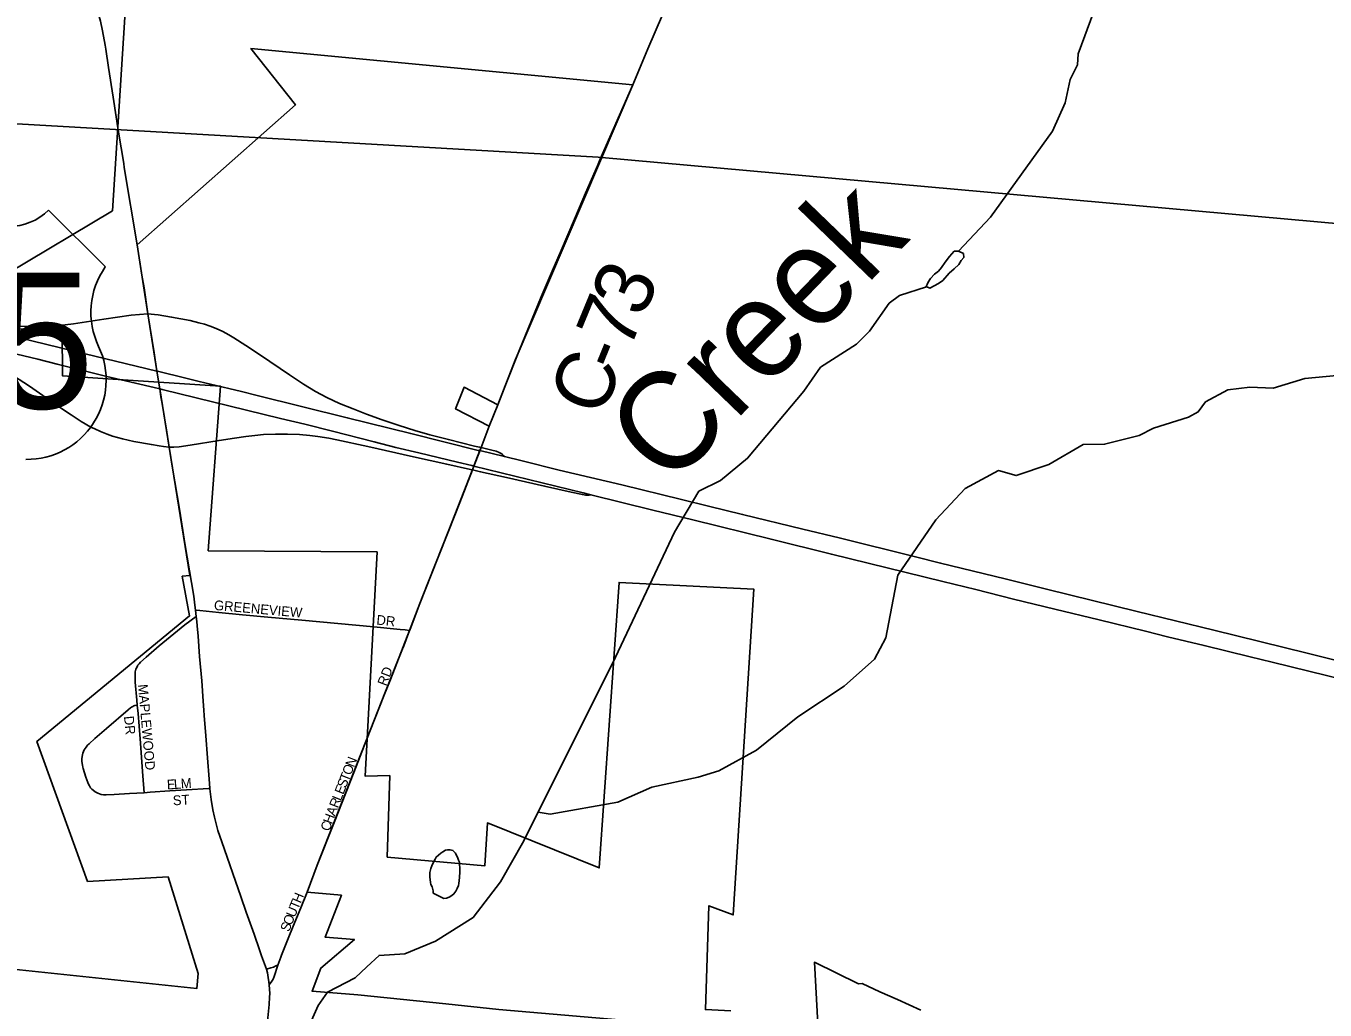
# Model space of a CAD drawing. Extents: x -5.4 to 49.9, y 13.2 to 48.4.
# Drawn here: x 29.333 to 30.593, y 43.891 to 44.845 of the extents above; entities that cross this region are included whole.
import ezdxf

# ---------------------------------------------------------------- set-up
doc = ezdxf.new("R2010")
doc.units = 0
for name, color, linetype in [('GM_X_City_Street', 7, 'Continuous'), ('GM_X_City_Street_Text', 7, 'Continuous'), ('GM_X_Corporation', 7, 'Continuous'), ('GM_X_County_Road', 7, 'Continuous'), ('GM_X_County_Road_Text', 7, 'Continuous'), ('GM_X_Interchange_Ramps', 7, 'Continuous'), ('GM_X_Major_River', 7, 'Continuous'), ('GM_X_Major_River_Text', 7, 'Continuous'), ('GM_X_Minor_Lake', 7, 'Continuous'), ('GM_X_Minor_River', 7, 'Continuous'), ('GM_X_State_Route', 7, 'Continuous'), ('GM_X_Township', 7, 'Continuous'), ('GM_X_US_Route', 7, 'Continuous'), ('GM_X_US_Shield', 7, 'Continuous')]:
    doc.layers.add(name, color=color, linetype=linetype)

msp = doc.modelspace()

# ---------------------------------------------------------------- linework, layer by layer
at = {"layer": 'GM_X_City_Street'}
for points in [[(29.4977, 44.2784), (29.502, 44.278), (29.5205, 44.2761), (29.5434, 44.2739), (29.5679, 44.2716), (29.6008, 44.2686), (29.6356, 44.2654), (29.6705, 44.2621), (29.693, 44.26), (29.6963, 44.2596), (29.701, 44.2591), (29.7053, 44.2586)], [(29.7053, 44.2586), (29.7055, 44.259), (29.7153, 44.2849)], [(29.4412, 44.1863), (29.4407, 44.1911), (29.4392, 44.2084), (29.4391, 44.2148), (29.4391, 44.2171), (29.4392, 44.2186), (29.4394, 44.2197), (29.4399, 44.2212), (29.4407, 44.2228), (29.4414, 44.2242), (29.4419, 44.225), (29.4431, 44.2264), (29.4444, 44.2278), (29.4498, 44.2328), (29.4626, 44.2436), (29.4874, 44.2641), (29.4983, 44.2721)], [(29.6985, 44.2409), (29.6997, 44.2438), (29.7053, 44.2586)], [(29.5812, 43.9436), (29.5877, 43.9598), (29.5925, 43.9719), (29.6, 43.9896), (29.6061, 44.0047), (29.6157, 44.0309), (29.6322, 44.0725), (29.6511, 44.121), (29.6636, 44.1526), (29.682, 44.1994), (29.6985, 44.2409)], [(29.448, 44.1013), (29.4338, 44.1004), (29.4189, 44.0994), (29.411, 44.0991), (29.4086, 44.0993), (29.4064, 44.0996), (29.4046, 44.1001), (29.403, 44.1007), (29.4017, 44.1014), (29.4003, 44.1022), (29.3984, 44.1037), (29.3971, 44.1048), (29.396, 44.1061), (29.3949, 44.1078), (29.394, 44.1097), (29.3932, 44.1113), (29.3914, 44.1163), (29.3901, 44.1205), (29.3887, 44.1248), (29.3884, 44.1261), (29.3881, 44.1279), (29.3879, 44.1295), (29.3876, 44.1318), (29.3876, 44.134), (29.3878, 44.1365), (29.3881, 44.1381), (29.3885, 44.1396), (29.3891, 44.1414), (29.3899, 44.1429), (29.3906, 44.1443), (29.3916, 44.1456), (29.393, 44.1473), (29.3945, 44.1488), (29.4001, 44.1538), (29.4115, 44.1635), (29.4324, 44.1816), (29.4346, 44.1835), (29.4356, 44.1842), (29.4368, 44.1849), (29.438, 44.1854), (29.439, 44.1858), (29.4405, 44.1861), (29.4412, 44.1863)], [(29.448, 44.1013), (29.4466, 44.1177), (29.4442, 44.1535), (29.4421, 44.1781), (29.4412, 44.1863)], [(29.5117, 44.1056), (29.5106, 44.1055), (29.4889, 44.1042), (29.4727, 44.103), (29.4539, 44.1017), (29.448, 44.1013)], [(29.5665, 43.9303), (29.5708, 43.9315), (29.5733, 43.9322), (29.5756, 43.9333), (29.5777, 43.9342)], [(29.5691, 43.9149), (29.5718, 43.9186), (29.5729, 43.9204), (29.5739, 43.923), (29.5777, 43.9342)], [(29.5777, 43.9342), (29.5804, 43.9418), (29.5812, 43.9436)]]:
    msp.add_lwpolyline(points, dxfattribs=at)
at = {"layer": 'GM_X_Corporation'}
for points in [[(29.3154, 44.6047), (29.4173, 44.6657), (29.4494, 45.1735)], [(29.2715, 43.9353), (29.4989, 43.9114), (29.5002, 43.926), (29.4712, 44.0196), (29.3931, 44.0152), (29.344, 44.151), (29.492, 44.2727), (29.4849, 44.3112), (29.4923, 44.3118), (29.4722, 44.4364), (29.4632, 44.493), (29.4603, 44.5103), (29.4516, 44.5657), (29.441, 44.6327), (29.5946, 44.7683), (29.5515, 44.8229), (29.9217, 44.7877), (29.8078, 44.5206), (29.7907, 44.4775), (29.7582, 44.4945), (29.7499, 44.4734), (29.7826, 44.4566), (29.7746, 44.4361), (29.7434, 44.3558), (29.7176, 44.2907), (29.7153, 44.2849), (29.7053, 44.2586), (29.6867, 44.2112), (29.6803, 44.1951), (29.6497, 44.1173), (29.6157, 44.0309), (29.6061, 44.0047), (29.6392, 44.0018), (29.6233, 43.9613), (29.6518, 43.959), (29.6194, 43.9312), (29.6107, 43.9088), (29.6551, 43.9053), (29.7403, 43.8965), (29.7917, 43.8912), (29.9386, 43.8783)], [(30.0169, 43.8897), (29.9921, 43.8909), (29.9955, 43.9916), (30.0191, 43.9827), (30.039, 44.2987), (29.9085, 44.3052), (29.8892, 44.0283), (29.7807, 44.072), (29.7782, 44.0303), (29.6837, 44.0388), (29.6861, 44.1179), (29.6623, 44.1172), (29.6738, 44.3348), (29.5101, 44.3359), (29.522, 44.4955), (29.4373, 44.5011), (29.3686, 44.5056), (29.3684, 44.5486), (29.3122, 44.5522)], [(30.2009, 43.8905), (30.1785, 43.9007), (30.1611, 43.9081), (30.1441, 43.9164), (30.1407, 43.9159), (30.0978, 43.9368), (30.1172, 43.5785)]]:
    msp.add_lwpolyline(points, dxfattribs=at)
at = {"layer": 'GM_X_County_Road'}
for points in [[(29.9217, 44.7877), (29.9364, 44.8225), (29.9506, 44.8556), (29.9779, 44.9189), (29.9868, 44.9401), (29.994, 44.9586), (30.001, 44.9779), (30.0071, 44.9962), (30.0139, 45.0188), (30.0224, 45.046), (30.0463, 45.1218), (30.0595, 45.1646), (30.0669, 45.1887)], [(29.8874, 44.7093), (29.8901, 44.7156), (29.9217, 44.7877)], [(29.876, 44.6828), (29.8874, 44.7093)], [(29.7907, 44.4775), (29.7981, 44.4958), (29.8112, 44.5293), (29.8329, 44.5821), (29.8436, 44.6072), (29.8522, 44.6272), (29.8651, 44.6574), (29.876, 44.6828)], [(29.7826, 44.4566), (29.7907, 44.4775)], [(29.7153, 44.2849), (29.7325, 44.3282), (29.743, 44.3548), (29.7539, 44.3826), (29.7662, 44.4143), (29.7676, 44.418), (29.7689, 44.4214), (29.7734, 44.433), (29.7746, 44.436), (29.7826, 44.4566)]]:
    msp.add_lwpolyline(points, dxfattribs=at)
at = {"layer": 'GM_X_Interchange_Ramps'}
for points in [[(29.4516, 44.5657), (29.4352, 44.5643), (29.4087, 44.5606), (29.3794, 44.5559), (29.3713, 44.5549), (29.3624, 44.554), (29.3541, 44.5536), (29.3422, 44.5532), (29.328, 44.5538), (29.3153, 44.555), (29.3041, 44.5563), (29.2957, 44.5579), (29.2846, 44.56), (29.2094, 44.5769), (29.1748, 44.5845), (29.1419, 44.5917), (29.1104, 44.5986), (29.0873, 44.6039), (29.0812, 44.6051), (29.0773, 44.6056), (29.0752, 44.6056), (29.072, 44.6049)], [(29.7974, 44.4272), (29.7957, 44.4287), (29.7946, 44.4298), (29.7921, 44.4313), (29.7891, 44.4324), (29.785, 44.4336), (29.7746, 44.436), (29.7731, 44.4364), (29.7683, 44.4375), (29.7429, 44.4438), (29.7249, 44.4483), (29.7105, 44.4524), (29.6951, 44.4573), (29.6786, 44.4629), (29.6634, 44.4685), (29.6507, 44.4734), (29.6374, 44.4788), (29.625, 44.4846), (29.614, 44.4904), (29.6023, 44.4975), (29.5888, 44.5064), (29.5606, 44.5257), (29.5466, 44.5349), (29.535, 44.5425), (29.5299, 44.5454), (29.5243, 44.5484), (29.5176, 44.5515), (29.512, 44.5537), (29.5064, 44.5556), (29.5009, 44.5571), (29.4927, 44.5591), (29.4745, 44.5625), (29.4615, 44.5646), (29.4579, 44.565), (29.4516, 44.5657)], [(29.3211, 44.5057), (29.3367, 44.4955), (29.3668, 44.4745), (29.3771, 44.4676), (29.387, 44.4612), (29.3962, 44.4559), (29.4001, 44.454), (29.4056, 44.4515), (29.412, 44.4489), (29.4174, 44.4471), (29.427, 44.4445), (29.4379, 44.442), (29.455, 44.4389), (29.4624, 44.4377), (29.4666, 44.4371), (29.4722, 44.4364)], [(29.4722, 44.4364), (29.4768, 44.4364), (29.482, 44.4367), (29.4924, 44.4382), (29.5206, 44.443), (29.5354, 44.4452), (29.5466, 44.4467), (29.5552, 44.4477), (29.5637, 44.4485), (29.5752, 44.4489), (29.587, 44.4489), (29.5985, 44.4485), (29.6085, 44.4476), (29.6162, 44.4467), (29.6271, 44.4451), (29.6347, 44.4436), (29.6648, 44.437), (29.7091, 44.4269), (29.7413, 44.4198), (29.7643, 44.4148), (29.7662, 44.4143), (29.7742, 44.4126), (29.7993, 44.4069), (29.8362, 44.3987), (29.8621, 44.3927), (29.8729, 44.3904), (29.8761, 44.3898), (29.8777, 44.3897), (29.8792, 44.3898), (29.881, 44.3902)]]:
    msp.add_lwpolyline(points, dxfattribs=at)
at = {"layer": 'GM_X_Major_River'}
for points in [[(30.2375, 44.6265), (30.2685, 44.6593), (30.3288, 44.7428), (30.341, 44.7703), (30.3457, 44.793), (30.3528, 44.8073), (30.3537, 44.8179), (30.3689, 44.859), (30.3758, 44.9196), (30.3869, 44.9463), (30.4033, 44.9707), (30.4248, 44.9881), (30.4363, 44.9955), (30.479, 45.0086), (30.498, 45.0333), (30.5209, 45.0416), (30.533, 45.0433), (30.5572, 45.0409), (30.5955, 45.0264), (30.6083, 45.0227), (30.6821, 45.0083), (30.6919, 45.0043), (30.7325, 44.9739)], [(30.2375, 44.6265), (30.2334, 44.6263), (30.2287, 44.6214), (30.2245, 44.6158), (30.2209, 44.6106), (30.2182, 44.6072), (30.2144, 44.6042), (30.2105, 44.6001), (30.2082, 44.5964), (30.207, 44.5941), (30.2062, 44.5922), (30.2096, 44.5907), (30.218, 44.595), (30.2222, 44.598), (30.2284, 44.6051), (30.2334, 44.6092), (30.2377, 44.6136), (30.24, 44.6174), (30.2427, 44.6204), (30.2424, 44.6242)], [(30.2424, 44.6242), (30.2375, 44.6265)], [(29.5954, 43.8468), (29.6165, 43.895), (29.6258, 43.9077), (29.6525, 43.9216), (29.6637, 43.9324), (29.6757, 43.9435), (29.7007, 43.9449), (29.7304, 43.9572), (29.7668, 43.9804), (29.7933, 44.0148), (29.816, 44.0546), (29.9051, 44.2327), (29.962, 44.3538), (29.9858, 44.3936), (30.0068, 44.4042), (30.033, 44.4256), (30.0876, 44.4906), (30.1036, 44.5138), (30.1385, 44.5363), (30.1512, 44.5489), (30.1703, 44.5759), (30.1803, 44.5833), (30.2066, 44.592)]]:
    msp.add_lwpolyline(points, dxfattribs=at)
at = {"layer": 'GM_X_Minor_Lake'}
for points in [[(30.2375, 44.6265), (30.2685, 44.6593), (30.3288, 44.7428), (30.341, 44.7703), (30.3457, 44.793), (30.3528, 44.8073), (30.3537, 44.8179), (30.3689, 44.859), (30.3758, 44.9196), (30.3869, 44.9463), (30.4033, 44.9707), (30.4248, 44.9881), (30.4363, 44.9955), (30.479, 45.0086), (30.498, 45.0333), (30.5209, 45.0416), (30.533, 45.0433), (30.5572, 45.0409), (30.5955, 45.0264), (30.6083, 45.0227), (30.6821, 45.0083), (30.6919, 45.0043), (30.7325, 44.9739)], [(29.7282, 44.0038), (29.7282, 44.0061), (29.7271, 44.0099), (29.726, 44.0122), (29.7257, 44.0141), (29.7253, 44.0172), (29.725, 44.0195), (29.725, 44.0221), (29.725, 44.024), (29.7258, 44.0278), (29.727, 44.0305), (29.7285, 44.0339), (29.7301, 44.0369), (29.7312, 44.0388), (29.7332, 44.0406), (29.7355, 44.0425), (29.7374, 44.044), (29.74, 44.0455), (29.7423, 44.0459), (29.7446, 44.0458), (29.7473, 44.0454), (29.7499, 44.0427), (29.7521, 44.0378), (29.7528, 44.0359), (29.7536, 44.034), (29.7536, 44.0313), (29.7539, 44.0286), (29.7539, 44.0245), (29.7538, 44.0191), (29.7534, 44.0161), (29.753, 44.0134), (29.7526, 44.0112), (29.7514, 44.0085), (29.7502, 44.0059), (29.7483, 44.0032), (29.7464, 44.0017), (29.7437, 43.9999), (29.7411, 43.9991), (29.7384, 43.9988), (29.7282, 44.0038)]]:
    msp.add_lwpolyline(points, dxfattribs=at)
at = {"layer": 'GM_X_Minor_River'}
msp.add_lwpolyline([(29.8299, 44.0824), (29.8415, 44.0805), (29.9073, 44.0922), (29.9401, 44.1068), (29.985, 44.1163), (30.0052, 44.1224), (30.0416, 44.1426), (30.0816, 44.1749), (30.1268, 44.2045), (30.1561, 44.2309), (30.1671, 44.2516), (30.1787, 44.3122), (30.2157, 44.3658), (30.2439, 44.3964), (30.2764, 44.4137), (30.2934, 44.4088), (30.325, 44.4197), (30.3584, 44.4388), (30.3792, 44.4392), (30.4127, 44.4477), (30.4265, 44.4547), (30.4604, 44.4654), (30.47, 44.4706), (30.4769, 44.4803), (30.4988, 44.4921), (30.52, 44.4947), (30.5427, 44.4936), (30.5732, 44.5029), (30.6044, 44.5058)], dxfattribs=at)
at = {"layer": 'GM_X_State_Route'}
for points in [[(29.4107, 44.8223), (29.4101, 44.8261), (29.4075, 44.8402), (29.4055, 44.8494), (29.4025, 44.8608), (29.4001, 44.8686), (29.3942, 44.8856), (29.3829, 44.9162)], [(29.4653, 44.4788), (29.4642, 44.4853), (29.463, 44.493), (29.4603, 44.5101), (29.4575, 44.5277), (29.4516, 44.5657), (29.4478, 44.5909), (29.4456, 44.6032), (29.441, 44.6327), (29.4287, 44.7077), (29.4281, 44.7114), (29.4231, 44.742), (29.4179, 44.7758), (29.4135, 44.8046), (29.4107, 44.8223)], [(29.4977, 44.2784), (29.4972, 44.2832), (29.4961, 44.2918), (29.4875, 44.3431), (29.4825, 44.3744), (29.4752, 44.4179), (29.4722, 44.4364), (29.4698, 44.451), (29.4653, 44.4788)], [(29.4993, 44.2632), (29.4989, 44.2674), (29.4983, 44.2721), (29.4977, 44.2784)], [(29.5688, 43.918), (29.5683, 43.9222), (29.5674, 43.9265), (29.5665, 43.9303), (29.5618, 43.943), (29.5599, 43.9488), (29.5547, 43.9642), (29.5469, 43.9856), (29.5417, 44.0007), (29.5231, 44.0537), (29.5195, 44.0646), (29.5177, 44.0711), (29.516, 44.0775), (29.5145, 44.0846), (29.5128, 44.0948), (29.5117, 44.105), (29.5117, 44.1056), (29.5109, 44.1145), (29.5094, 44.1351), (29.5078, 44.1566), (29.5062, 44.1763), (29.5059, 44.1812), (29.5053, 44.1901), (29.5037, 44.2098), (29.5017, 44.2333), (29.5002, 44.2531), (29.4993, 44.2632)], [(29.5504, 43.7165), (29.5506, 43.7191), (29.5544, 43.756), (29.557, 43.7806), (29.5676, 43.8796), (29.5691, 43.8959), (29.5696, 43.903), (29.5697, 43.9066), (29.5691, 43.9149), (29.5688, 43.918)]]:
    msp.add_lwpolyline(points, dxfattribs=at)
at = {"layer": 'GM_X_Township'}
for points in [[(28.0105, 47.4437), (27.6877, 47.1657), (27.6499, 47.1327), (27.6308, 47.1161), (28.089, 46.5424), (27.3995, 45.9845), (27.4216, 45.9826), (27.5161, 45.979), (27.573, 45.9769), (27.6274, 45.9769), (27.7195, 46.0028), (27.6935, 45.0509), (27.691, 44.9621), (27.6878, 44.8437), (27.7914, 44.8377), (29.42, 44.7443), (29.8881, 44.7175), (31.3945, 44.5822), (32.3292, 44.4982), (33.0771, 44.431)], [(31.3945, 44.5822), (29.8881, 44.7175), (29.42, 44.7443), (27.7914, 44.8377)]]:
    msp.add_lwpolyline(points, dxfattribs=at)
at = {"layer": 'GM_X_US_Route'}
for points in [[(29.3017, 44.5485), (29.3391, 44.5394), (29.3802, 44.5294), (29.4603, 44.5101), (29.4623, 44.5096), (29.4871, 44.5035), (29.5013, 44.5001), (29.5122, 44.4975), (29.5424, 44.4902), (29.5575, 44.4865), (29.6449, 44.4649), (29.7065, 44.4495), (29.7719, 44.4333), (29.7734, 44.433), (29.7974, 44.4272), (29.8144, 44.4231), (29.8503, 44.4142), (29.9111, 44.3998), (29.969, 44.3856), (29.995, 44.3792), (30.0282, 44.3711), (30.0867, 44.3568), (30.1218, 44.3483), (30.1959, 44.3299), (30.2201, 44.324), (30.2828, 44.3086), (30.3227, 44.2987), (30.4107, 44.2771), (30.485, 44.259), (30.5755, 44.2366), (30.6322, 44.2225)], [(29.3176, 44.5281), (29.3449, 44.5216), (29.3636, 44.517), (29.4118, 44.5049), (29.4576, 44.4942)], [(29.4576, 44.4942), (29.463, 44.493), (29.4654, 44.4924)], [(29.4654, 44.4924), (29.5801, 44.4643), (29.6036, 44.4586), (29.6307, 44.4518), (29.671, 44.4416), (29.6921, 44.4362), (29.7143, 44.4308), (29.7518, 44.4218), (29.7655, 44.4185)], [(29.7655, 44.4185), (29.7676, 44.418), (29.8736, 44.392), (29.881, 44.3902), (29.9412, 44.3753), (29.9798, 44.3658), (30.0558, 44.347), (30.1143, 44.3326), (30.2223, 44.3061), (30.2543, 44.2982), (30.291, 44.2891), (30.3309, 44.2793), (30.3738, 44.269), (30.419, 44.2579), (30.4401, 44.2526), (30.4757, 44.2439), (30.5204, 44.233), (30.5415, 44.228), (30.6127, 44.2105)]]:
    msp.add_lwpolyline(points, dxfattribs=at)
at = {"layer": 'GM_X_US_Shield'}
msp.add_line((29.4103, 44.6112), (29.3553, 44.6662), dxfattribs=at)
for centre, radius, start, end in [((29.3169, 44.7054), 0.0549, 225.573, 314.427), ((29.4732, 44.5671), 0.0769, 144.9991, 205.4529), ((29.3342, 44.5014), 0.0769, 269.3617, 25.1681)]:
    msp.add_arc(centre, radius, start, end, dxfattribs=at)

# ---------------------------------------------------------------- texts
at = {"layer": 'GM_X_City_Street_Text'}
for s, rotation, p in [('GREENEVIEW', 354.9767, (29.5153, 44.2786)), ('DR', 353.9946, (29.6728, 44.2644)), ('RD', 68.7471, (29.6826, 44.2041)), ('MAPLEWOOD', 275.0786, (29.4419, 44.2061)), ('DR', 276.0054, (29.4283, 44.1753)), ('N', 68.5435, (29.6514, 44.1253)), ('O', 68.5665, (29.6483, 44.1175)), ('E', 3.007, (29.4702, 44.1044)), ('L', 4.283, (29.4771, 44.1048)), ('M', 4.3877, (29.4838, 44.1053)), ('S', 68.5486, (29.6434, 44.1051)), ('T', 68.5486, (29.6459, 44.1113)), ('ST', 3.5746, (29.476, 44.089)), ('L', 68.5486, (29.6386, 44.0927)), ('E', 68.5486, (29.641, 44.0989)), ('A', 68.6126, (29.6328, 44.078)), ('R', 68.5458, (29.6358, 44.0857)), ('C', 71.4422, (29.6276, 44.0632)), ('H', 69.733, (29.6299, 44.0702)), ('T', 67.3717, (29.5971, 43.9873)), ('H', 67.3667, (29.5997, 43.9934)), ('U', 67.3869, (29.5939, 43.9796)), ('S', 69.0762, (29.5884, 43.9657)), ('O', 67.8374, (29.5908, 43.9719))]:
    msp.add_text(s, height=0.00947, rotation=rotation, dxfattribs=at).set_placement(p)
at = {"layer": 'GM_X_County_Road_Text'}
for s, rotation, p in [('3', 66.513, (29.9311, 44.5606)), ('7', 67.5579, (29.9179, 44.5285)), ('C', 67.8833, (29.8915, 44.4638)), ('-', 67.8101, (29.9091, 44.507))]:
    msp.add_text(s, height=0.0568, rotation=rotation, dxfattribs=at).set_placement(p)
at = {"layer": 'GM_X_Major_River_Text'}
msp.add_text('Creek', height=0.09471, rotation=46.0163, dxfattribs=at).set_placement((29.957, 44.395))
at = {"layer": 'GM_X_US_Shield'}
msp.add_text('35', height=0.13184, dxfattribs=at).set_placement((29.2034, 44.4739))

doc.saveas('drawing.dxf')
